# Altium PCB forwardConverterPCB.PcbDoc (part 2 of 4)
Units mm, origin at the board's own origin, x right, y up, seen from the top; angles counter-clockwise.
Board outline 382.81 x 370.12 mm, 8 copper layers (L1, L2 (GND), L3, L4, L5(GND), L6, L7 (GND), L8), stack 1.028 mm thick; 352 components, 187 nets, 1188 pads, 1016 vias.
Unrouted connection lines stored in the file: 19.
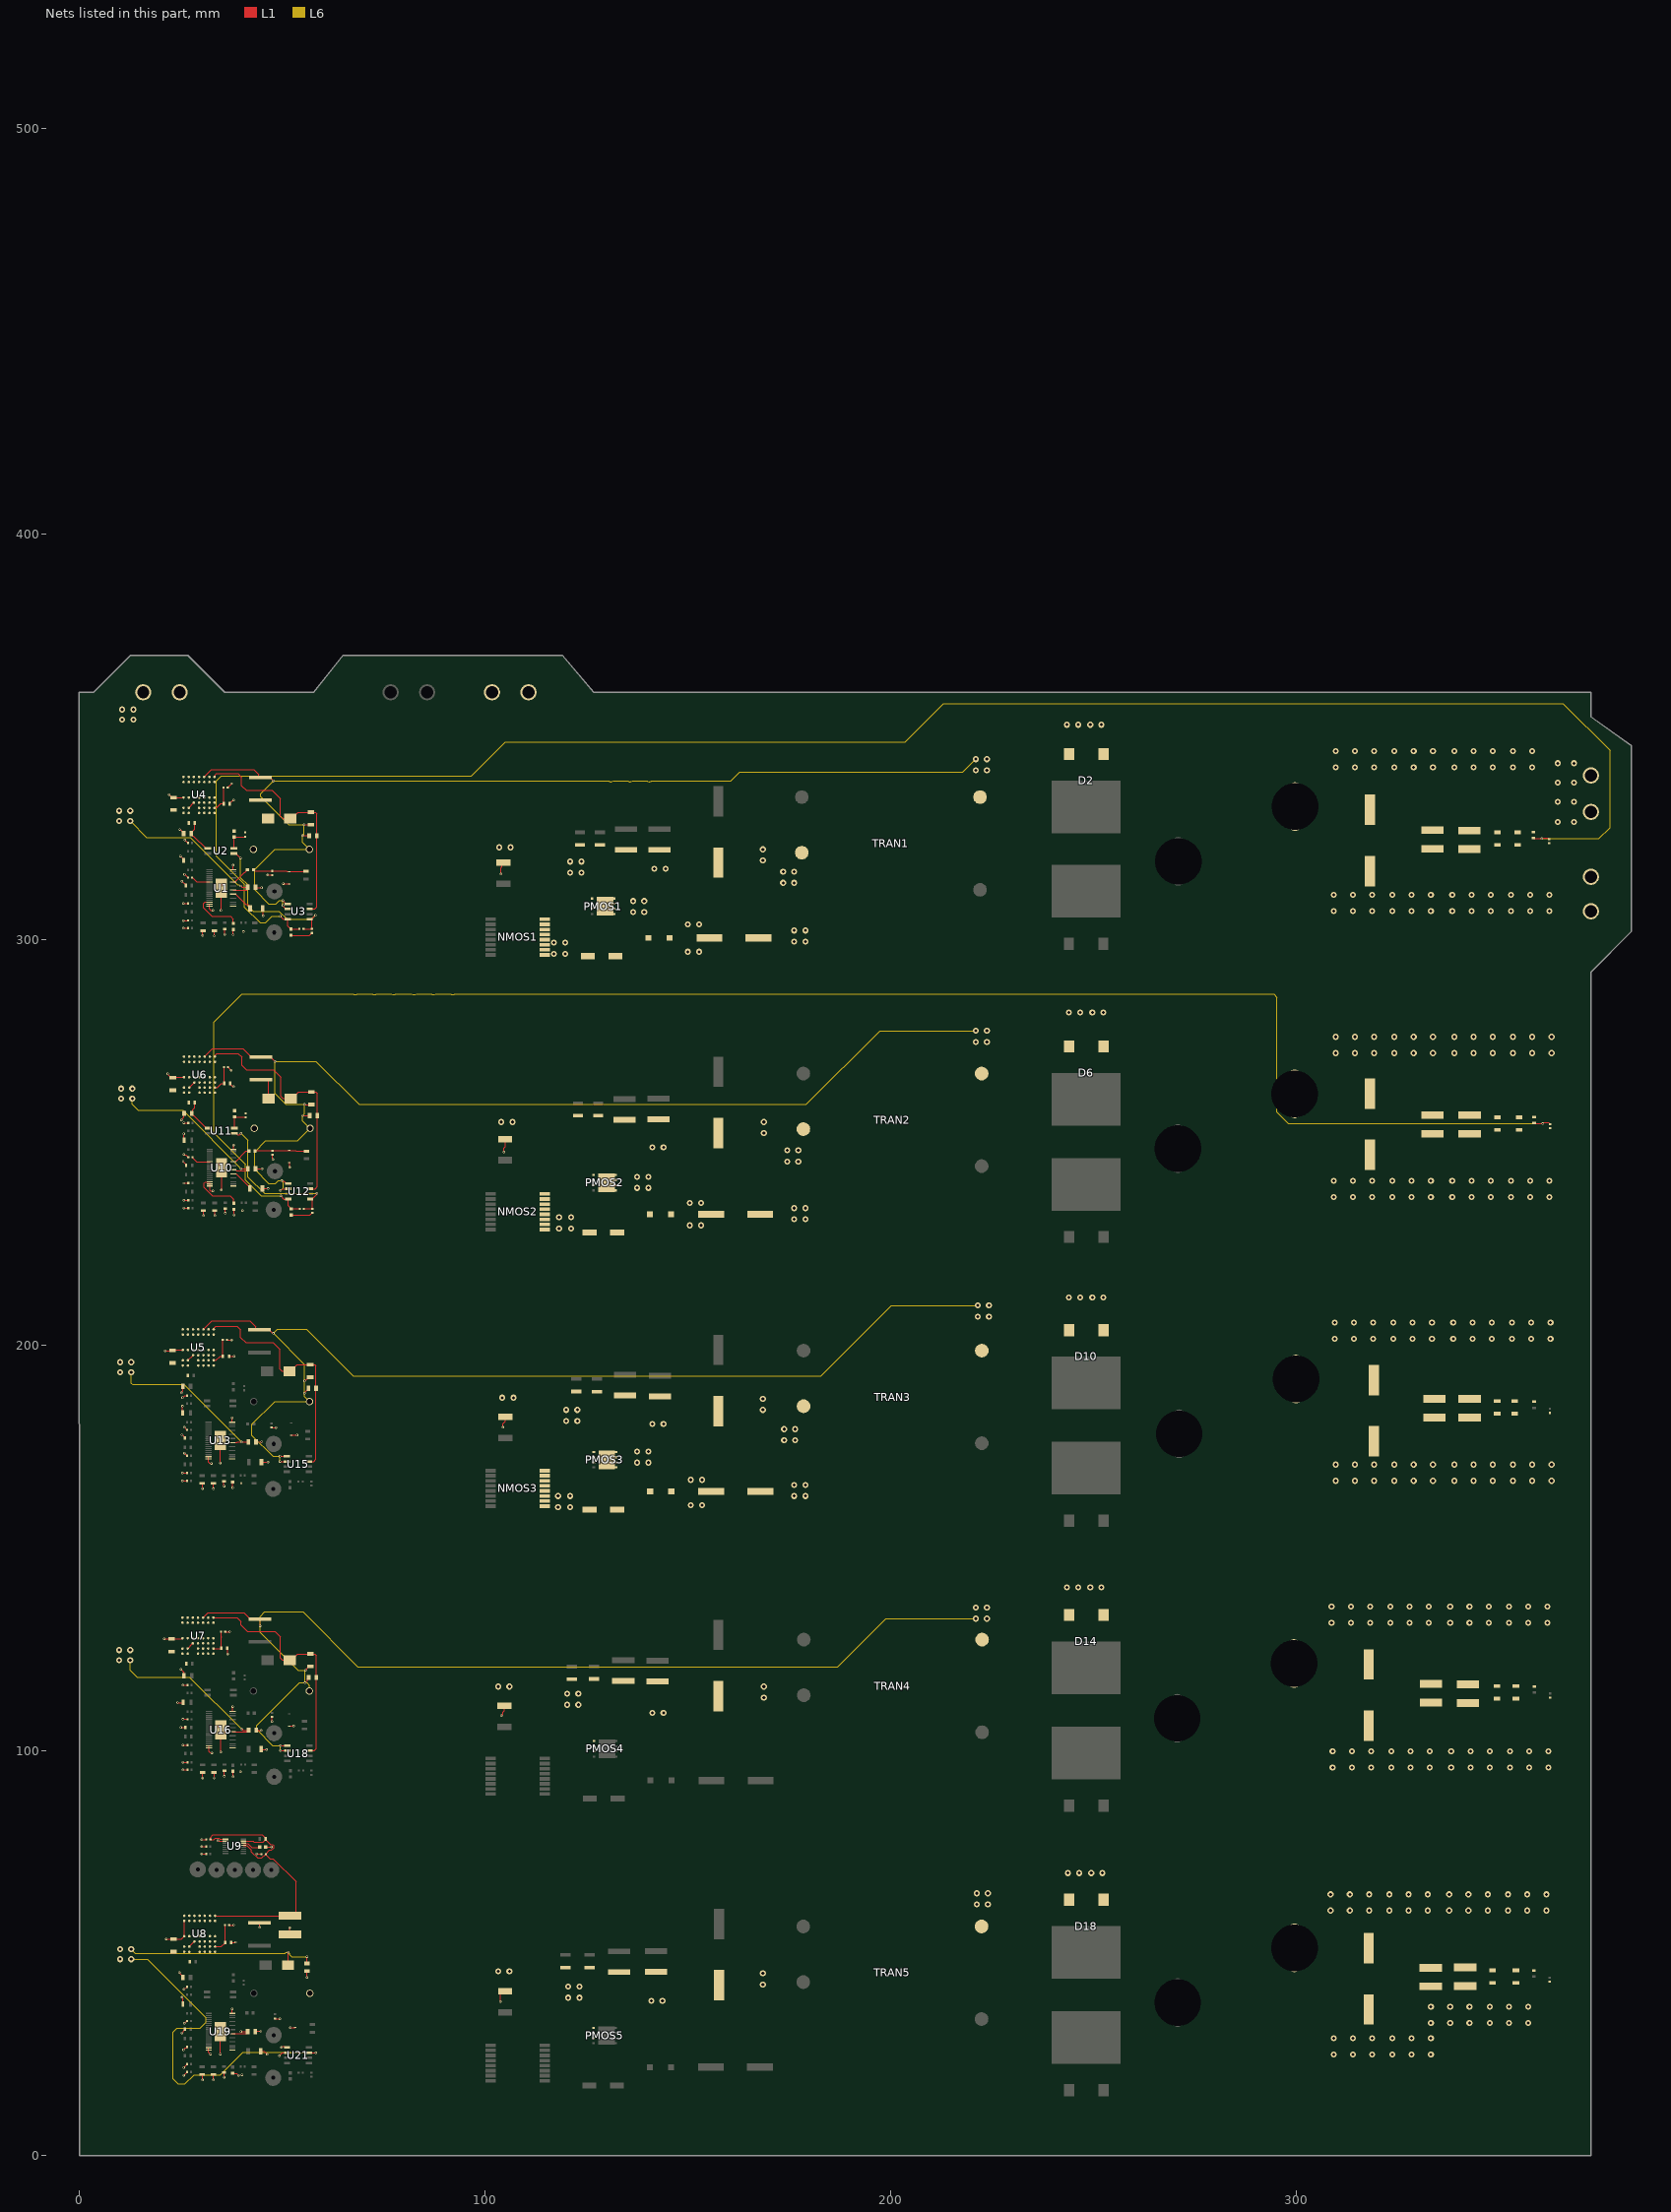
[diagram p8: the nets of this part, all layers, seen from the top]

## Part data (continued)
C25 C27 C31 C33 C38: "50V 10uF X7R ±10% 1206 Multilayer Ceramic Capacitors MLCC - SMD/SMT ROHS", Case Code (Imperial)=1206, Case Code (Metric)=3216, Dielectric=X7R, Dielectric Material=Ceramic, Manufacturer="Samsung Electro-Mechanics", Max Operating Temperature=125°C, Min Operating Temperature=-55°C, Supplier Part Number=1276-6767-1-ND, Tolerance=10%, Voltage Rating=50V
C28 C29 C34 C35 C41: "0402 10 pF 6.3 V ±10 % Tolerance C0G/NP0 SMT Multilayer Ceramic Capacitor", Case Code (Imperial)=0402, Case Code (Metric)=1005, Dielectric=C0G, Dielectric Material=Ceramic, Manufacturer="KYOCERA AVX", Max Operating Temperature=125°C, Min Operating Temperature=-55°C, Supplier Part Number=478-12646-1-ND, Tolerance=10%, Voltage Rating=6.3V
C36 C37: "10V 100nF X7R ±10% 0402 Multilayer Ceramic Capacitors MLCC - SMD/SMT ROHS", Dielectric Material=Ceramic, Manufacturer="Cal-Chip Electronics", Max Operating Temperature=125°C, Min Operating Temperature=-55°C, Supplier Part Number=4713-GMC04X7R104K10NTCT-ND, Voltage Rating (DC)=10V
D1 D2 D5 D6 D9 D10 D13 D14 D17 D18: library part DSEP60-06AZ-TRL, "Power Diode Discretes-FRED TO-", Manufacturer=IXYS, Supplier Part Number=238-DSEP60-06AZ-TRLCT-ND
D3 D7 D11 D15 D19: "Rectifier Diode, Schottky, 1 Phase, 1 Element, 0.5A, 100V V(RRM), Silicon", Forward Voltage=850mV, Manufacturer=MCC, Max Forward Surge Current (Ifsm)=5.5A, Max Operating Temperature=150°C, Max Output current=500mA, Min Breakdown Voltage=100V, Min Operating Temperature=-55°C, Peak Reverse Current=1µA, Supplier Part Number=353-B05100W-TPCT-ND
D4 D8 D12 D16 D20: "Zener Diode Single 4.7V 5% 2Ohm 5000mW 2-Pin Case 017AA-01 T/R / DIODE ZENER 4.7V 5W AXIAL", Case/Package=Axial, Forward Voltage=1.2V, Manufacturer=onsemi, Manufacturer Lifecycle Status=ACTIVE, Max Operating Temperature=200°C, Max Power Dissipation=5W, Max Reverse Leakage Current=5µA, Min Operating Temperature=-65°C, Reference Voltage=4.7V, Supplier Part Number=1N5337, Test Current=260mA, Tolerance=5%
J1 J2 J3 J4 J5 J6 J7 J8 J9 J10: "ReelFast Surface Mount Nuts and Spacers/Standoffs -br Type SMTSO - Unified", Current Rating=36A, Manufacturer=PennEngineering, Supplier Part Number=153-SMTSO-116-8ET
L1 L2 L3 L4 L5: "Fixed Ind 33UH 52A 1.88 Mohm Th", Manufacturer=Codaca, Supplier Part Number=4044-CPEX4141L-330MC-ND
NMOS1 NMOS2 NMOS3 NMOS4 NMOS5: "Mosfet N-ch 200V 130A 280W Tolt", Manufacturer=GoFord, Supplier Part Number=3141-GT100N20TTCT-ND
PMOS1 PMOS2 PMOS3 PMOS4 PMOS5: "P-150V, -60A, RD(max) Less Than 80mOhm at -10V, VTH -1V to -4V, DFN5x6-8L", Manufacturer=GoFord, Manufacturer Lifecycle Status=ACTIVE, Supplier Part Number=3141-G900P15D5CT-ND
R1 R34 R59 R84 R109: "SM Series 3.9 Ohm ±5 % 2 W ±200 ppm/°C Surface Mount Wirewound Resistor", Case Code (Imperial)=2616, Case Code (Metric)=6740, Insulation Resistance=10GΩ, Manufacturer="TE Connectivity", Manufacturer Lifecycle Status=ACTIVE, Max Operating Temperature=275°C, Max Power Dissipation=2W, Min Operating Temperature=-55°C, Number of Resistors=1, Operating Supply Voltage=300V, Supplier Part Number=A103596DKR-ND, Temperature Coefficient=200ppm/°C, Tolerance=5%
R2 R35 R60 R85 R110: "Res Thick Film 0805 82.5K Ohm 1% 1/8W ±100ppm/°C Molded SMD SMD Paper T/R", Case Code (Imperial)=0805, Case Code (Metric)=2012, Manufacturer="Stackpole Electronics", Max Operating Temperature=155°C, Max Power Dissipation=125mW, Min Operating Temperature=-55°C, Supplier Part Number=RMCF0805FT82K5CT-ND, Temperature Coefficient=100ppm/°C, Tolerance=1%, Voltage Rating=150V
R3 R7 R24 R25 R36 R40 R57 R58 R61 R65 R82 R83 R86 R90 R107 R108 R111 R115 R132 R133: "Zero Ohm Resistor, Jumper, 0805 [2012 Metric], Thick Film, 125 mW, 2.5 A, Surface Mount Device", Case Code (Imperial)=0805, Manufacturer=Vishay, Manufacturer Package Identifier=CRCW0805-e3, Max Operating Temperature=155°C, Max Power Dissipation=125mW, Min Operating Temperature=-55°C, Supplier Part Number=541-0.0ADKR-ND, Temperature Coefficient=100ppm/°C, Tolerance=1%, Voltage Rating=150V
R4 R23 R30 R31 R37 R56 R62 R81 R87 R106 R112 R131: "Fixed Resistor, Metal Glaze/thick Film, 0.0625W, 10000ohm, 50V, 1% +/-Tol, Surface Mount, 0402", Case/Package=0402, Manufacturer="Cal-Chip Electronics", Max Operating Temperature=155°C, Min Operating Temperature=-55°C, Power Dissipation=62.5mW, Power Rating=63mW, Supplier Part Number=4713-RM04F1002CT-ND, Temperature Coefficient=100ppm/°C, Tolerance=1%, Voltage Rating=50V
R5 R38 R63 R88 R113: "100mW Thick Film Resistors 75V ±100ppm/℃ ±1% 37.4kΩ 0603 Chip Resistor - Surface Mount ROHS", Case Code (Imperial)=0603, Manufacturer="Yageo Group", Max Operating Temperature=155°C, Max Power Dissipation=100mW, Min Operating Temperature=-55°C, Supplier Part Number=311-37.4KHRCT-ND, Temperature Coefficient=100ppm/°C, Tolerance=1%, Voltage Rating=75V, Voltage Rating (DC)=50V
R6 R39 R64 R89 R114: "Res Thick Film 0603 78.7K Ohm 1% 0.1W(1/10W) ±100ppm/C Pad SMD T/R", Case Code (Imperial)=0603, Manufacturer="Yageo Group", Max Operating Temperature=155°C, Max Power Dissipation=100mW, Min Operating Temperature=-55°C, Supplier Part Number=311-78.7KHRCT-ND, Temperature Coefficient=100ppm/°C, Tolerance=1%, Voltage Rating=75V, Voltage Rating (DC)=50V
R8 R41 R66 R91 R116: "Yageo RC0603FR-07100RL 0603 SMD Resistor 100 Ohm thin film chip resistor", Case Code (Imperial)=0603, Manufacturer="Yageo Group", Max Operating Temperature=155°C, Min Operating Temperature=-55°C, Power Dissipation=100mW, Supplier Part Number=311-100HRCT-ND, Temperature Coefficient=100ppm/°C, Tolerance=1%, Voltage Rating=75V, Voltage Rating (DC)=50V
R9 R11 R42 R44 R67 R69 R92 R94 R117 R119: "Res Thin Film 0402 5K Ohm 0.1% 0.05W(1/20W) +/-25ppm/C Sulfur Resistant Pad SMD Medical T/R", Case Code (Imperial)=0402, Case Code (Metric)=1005, Manufacturer=Vishay, Max Operating Temperature=155°C, Max Power Dissipation=50mW, Min Operating Temperature=-55°C, Supplier Part Number=541-1901-1-ND, Temperature Coefficient=25ppm/°C, Tolerance=0.1%, Working Voltage=75V
R10 R43 R68 R93 R118: "Res Thick Film 2512 1m Ohm 1% 2W ±75ppm/°C Molded SMD Embossed T/R", Case Code (Imperial)=2512, Case Code (Metric)=6432, Manufacturer=Bourns, Max Operating Temperature=170°C, Max Power Dissipation=2W, Min Operating Temperature=-55°C, Supplier Part Number=CRE2512-FZ-R001E-2CT-ND, Temperature Coefficient=50ppm/°C, Tolerance=1%
R12 R45 R70 R95 R120: "Res Thick Film 0603 13.3K Ohm 1% 0.1W(1/10W) ±100ppm/C Pad SMD Automotive T/R", Case Code (Imperial)=0603, Case Code (Metric)=1608, Manufacturer="Stackpole Electronics", Max Operating Temperature=155°C, Max Power Dissipation=100mW, Min Operating Temperature=-55°C, Supplier Part Number=RMCF0603FT13K3CT-ND, Temperature Coefficient=100ppm/°C, Tolerance=1%, Voltage Rating=75V
R13 R17 R18 R19 R46 R50 R51 R52 R71 R75 R76 R77 R96 R100 R101 R102 R121 R125 R126 R127: "62.5mW Thick Film Resistors ±100ppm/℃ ±1% 1kΩ 0402 Chip Resistor - Surface Mount ROHS", Manufacturer="Cal-Chip Electronics", Max Operating Temperature=155°C, Min Operating Temperature=-55°C, Power Dissipation=62.5mW, Supplier Part Number=4713-RM04F1001CT-ND, Temperature Coefficient=100ppm/°C, Tolerance=1%, Working Voltage=50V
R14 R47 R72 R97 R122: "Res Thick Film 0402 3K Ohm 1% 0.063W(1/16W) ±100ppm/C Pad SMD Automotive T/R", Case Code (Imperial)=0402, Case Code (Metric)=1005, Manufacturer="Yageo Group", Max Operating Temperature=155°C, Max Power Dissipation=63mW, Min Operating Temperature=-55°C, Power Dissipation=62.5mW, Supplier Part Number=YAG3485CT-ND, Temperature Coefficient=100ppm/°C, Tolerance=1%, Voltage Rating=50V
R15 R16 R48 R49 R73 R74 R98 R99 R123 R124: "Fixed Resistor, Metal Glaze/thick Film, 0.0625W, 100000ohm, 50V, 1% +/-Tol, Surface Mount, 0402", Manufacturer="Cal-Chip Electronics", Max Operating Temperature=155°C, Min Operating Temperature=-55°C, Power Dissipation=62.5mW, Supplier Part Number=4713-RM04F1003CT-ND, Temperature Coefficient=100ppm/°C, Tolerance=1%, Working Voltage=50V
R20 R53 R78 R103 R128: "Fixed Resistor, Wire Wound, 1W, 500ohm, 22.3607V, 1% +/-Tol, 20ppm/Cel, Surface Mount, 2515", Case Code (Imperial)=2515, Case Code (Metric)=6438, Manufacturer=Vishay, Max Operating Temperature=275°C, Min Operating Temperature=-65°C, Power Dissipation=1W, Supplier Part Number=541-WSC2515500R0FEBCT-ND, Temperature Coefficient=20ppm/°C, Tolerance=1%, Working Voltage=22.3607V
R21 R54 R79 R104 R129: "100mW Thick Film Resistors 75V ±100ppm/℃ ±1% 150kΩ 0603 Chip Resistor - Surface Mount ROHS", Case Code (Imperial)=0603, Manufacturer="Yageo Group", Max Operating Temperature=155°C, Max Power Dissipation=100mW, Min Operating Temperature=-55°C, Supplier Part Number=311-150KHRCT-ND, Temperature Coefficient=100ppm/°C, Tolerance=1%, Voltage Rating=75V, Voltage Rating (AC)=50V
R22 R55 R80 R105 R130: "Res Thick Film 0603 75K Ohm 1% 0.1W(1/10W) ±100ppm/C Pad SMD T/R Automotive AEC-Q200", Case Code (Imperial)=0603, Case Code (Metric)=1608, Manufacturer="Yageo Group", Max Operating Temperature=155°C, Max Power Dissipation=100mW, Min Operating Temperature=-55°C, Supplier Part Number=YAG3629CT-ND, Temperature Coefficient=100ppm/°C, Tolerance=1%, Voltage Rating=75V
R26 R27 R28 R29: "Fixed Resistor, Metal Glaze/thick Film, 0.1W, 3480ohm, 75V, 1% +/-Tol, Surface Mount, 0603", Manufacturer="Cal-Chip Electronics", Max Operating Temperature=155°C, Min Operating Temperature=-55°C, Power Dissipation=100mW, Supplier Part Number=4713-RM06F3481CT-ND, Temperature Coefficient=100ppm/°C, Tolerance=1%, Working Voltage=75V
R32: "100mW Thick Film Resistors 75V ±100ppm/℃ ±1% 402kΩ 0603 Chip Resistor - Surface Mount ROHS", Case Code (Imperial)=0603, Manufacturer="Yageo Group", Max Operating Temperature=155°C, Max Power Dissipation=100mW, Min Operating Temperature=-55°C, Supplier Part Number=311-402KHRCT-ND, Temperature Coefficient=100ppm/°C, Tolerance=1%, Voltage Rating=75V, Voltage Rating (DC)=50V
R33: "Res Thick Film 0603 11.8K Ohm 1% 0.1W(1/10W) ±100ppm/C Pad SMD Automotive T/R", Case Code (Imperial)=0603, Case Code (Metric)=1608, Manufacturer="KOA Speer", Max Operating Temperature=155°C, Min Operating Temperature=-55°C, Power Dissipation=100mW, Supplier Part Number=2019-RK73H1JTTD1182FCT-ND, Temperature Coefficient=100ppm/°C, Tolerance=1%, Voltage Rating=75V, Voltage Rating (DC)=50V
TRAN1 TRAN2 TRAN3 TRAN4 TRAN5: "Transformer, planar, for TI UCC28950, SMT, RoHS", Manufacturer=Coilcraft, Max Operating Temperature=120°C, Max Supply Voltage=60V, Min Input Voltage=38V, Min Operating Temperature=-40°C, Power Rating=800W
U1 U10 U13 U16 U19: "500kHz 8.5V~100V Buck-boost type 1 TSSOP-38-EP-4.4mm DC-DC Controllers ROHS", Case/Package=TSSOP, Frequency=500kHz, Manufacturer="Analog Devices", Manufacturer Lifecycle Status=PRODUCTION, Max Operating Temperature=150°C, Max Supply Voltage=100V, Min Operating Temperature=-40°C, Min Supply Voltage=8.5V, Nominal Supply Voltage=12V, Supplier Part Number=LT3753HFE#PBF-ND
U2 U11 U14 U17 U20: "Optocoupler DC-IN 1-CH Transistor DC-OUT 4-Pin SSOP T/R", Case/Package=SSOP, Collector Emitter Breakdown Voltage=80V, Collector Emitter Saturation Voltage=300mV, Current Transfer Ratio=50%, Dark Current=100nA, Forward Current=30mA, Forward Voltage=1.4V, Input Current=5mA, Isolation Voltage=2.5kV, Manufacturer=Renesas, Manufacturer Lifecycle Status=ACTIVE, Max Operating Temperature=100°C, Max Power Dissipation=120mW, Min Operating Temperature=-55°C, Reverse Breakdown Voltage=6V, Supplier Part Number=559-1038-1-ND
U3 U12 U15 U18 U21: "V-Ref Adjustable 2.5V to 36V 100mA 8-Pin SOIC N T/R", Cathode Current=1mA, Manufacturer="Analog Devices", Manufacturer Lifecycle Status=PRODUCTION, Max Operating Temperature=70°C, Max Output Voltage=36V, Min Operating Temperature=0°C, Min Output Voltage=2.5V, Output Current=100mA, Supplier Part Number=LT1431CS8#TRPBFCT-ND, Temperature Coefficient=30ppm/°C, Tolerance=0.4%
U4 U5 U6 U7 U8: "Module DC-DC 1-OUT 2.5V to 24V 0.45A 2.5W 38-Pin BGA Tray", Case/Package=BGA, Isolation Voltage=2kV, Manufacturer="Analog Devices", Manufacturer Lifecycle Status=PRODUCTION, Manufacturer Part Number=LTM8067EY#PBF67, Max Junction Temperature (Tj)=125°C, Max Output current=450mA, Max Output Voltage=24V, Max Supply Voltage=40V, Min Input Voltage=2.8V, Min Operating Temperature=-40°C, Min Output Voltage=2.5V, Min Supply Voltage=3V, Nominal Supply Current=7mA, Supplier Part Number=505-LTM8067EY#PBF-ND
U9: "1 to 8 Output, Multiphase Silicon Oscillator with Spread Spectrum Modulation", Case/Package=MSOP, Frequency=6.67MHz, Manufacturer="Analog Devices", Manufacturer Lifecycle Status=PRODUCTION, Max Junction Temperature (Tj)=150°C, Max Operating Temperature=125°C, Max Supply Voltage=5.5V, Min Operating Temperature=-40°C, Min Supply Voltage=2.7V, Operating Supply Current=2.4mA, Supplier Part Number=505-LTC6909HMS#TRPBFCT-ND

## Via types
v1: diameter 1.5, hole 0.75, L1 to L8, tented both sides, 800 vias
v2: diameter 0.6, hole 0.3, L1 to L8, tented both sides, 216 vias

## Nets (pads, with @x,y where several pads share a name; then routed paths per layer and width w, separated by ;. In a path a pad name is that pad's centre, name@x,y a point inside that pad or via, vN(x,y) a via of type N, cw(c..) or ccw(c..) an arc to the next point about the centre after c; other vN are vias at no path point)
+3.3V: C36.2 C37.2 C39.2 R32.1 U8.A6 U8.A7 U8.B6 U8.B7 U9.1 U9.13 U9.15 | length 76.5
  L1 w0.2: C37.2@32.285,78.023 33.186,78.023 33.463,78.3 34.349,78.3 34.536,78.113 U9.1@35.987,78.113 ; C37.2@32.285,78.113 32.285,78.535 32.9,79.15 45.05,79.15 45.9,78.3 R32.1@45.9,78.15 ; U8.A7@33.42,59.23 51.87,59.23 C39.2@51.9,59.2 53.4,59.2 53.4,67.652 47.752,73.3 47.008,73.3 C36.2@45.908,74.4 ; U9.13@40.411,76.613 40.461,76.563 41.248,76.563 42.35,75.461 42.35,75.002 43.901,73.45 44.958,73.45 C36.2@45.908,74.4 ; U9.15@40.411,77.613 42.818,77.613 43.03,77.4 45.3,77.4 45.9,78 47.1,76.8 47.6,76.8 47.9,76.5 47.9,75.951 47.341,75.392 46.9,75.392 C36.2@45.908,74.4
+12V: C13.2 C24.2 C26.2 C30.2 C32.2 C38.2 C54.2 C77.2 C100.2 C123.2 C133.2 J3.1 R8.2 R41.2 R66.2 R91.2 R116.2 R128.2 U1.28 U4.F3 U4.G1 U4.G2 U4.H1 U4.H2 U5.F3 U5.G1 U5.G2 U5.H1 U5.H2 U6.F3 U6.G1 U6.G2 U6.H1 U6.H2 U7.F3 U7.G1 U7.G2 U7.H1 U7.H2 U8.F3 U8.G1 U8.G2 U8.H1 U8.H2 U10.28 U13.28 U16.28 U19.28 U21.3 | length 313.4
  L1 w0.2: U7.G2@26.657,125.138 U7.F3@27.927,126.408 ; U5.G2@26.727,196.23 U5.F3@27.997,197.5 ; U4.G2@26.934,332.511 U4.F3@28.204,333.781 ; U6.G2@27.037,263.504 U6.F3@28.307,264.774 ; U8.G2@27.07,51.61 U8.F3@28.34,52.88 ; U13.28@37.65,175.942 38.892,175.942 39.007,176.057 v2(39.947,176.057) 41.618,176.057 C77.2@41.625,176.05 ; U19.28@37.663,30.121 41.1,30.121 41.45,30.471 C123.2@41.45,30.65 39.779,30.65 v2(39.772,30.657) ; U16.28@37.754,104.603 41.324,104.603 C100.2@41.674,104.953 ; U1.28@37.857,312.223 41.223,312.223 41.223,312.673 C13.2@41.475,312.925 40.083,312.925 39.783,313.225 v2(39.675,313.225) ; U10.28@37.96,243.216 38.57,243.216 38.61,243.176 38.61,243.117 38.727,243 41.15,243 41.5,243.35 C54.2@41.5,243.5 39.829,243.5 v2(39.822,243.507) ; v2(39.9,105.3) 40.008,105.3 40.356,104.953 C100.2@41.674,104.953 ; C100.2@41.674,105.003 C100.2@41.674,104.953 ; R128.2@51.425,47.025 51.475,47.075 v2(51.475,50.225) ; C133.2@56.1,47.45 56.1,49.121 v2(56.107,49.128) ; U21.3@56.575,25.448 58.246,25.448 v2(58.253,25.441)
  L6 w0.2: v1(12.5,122.25) 12.5,119.741 14.183,118.058 14.225,118.1 27.1,118.1 v2(39.9,105.3) ; v1(12.5,329.25) 16.55,325.2 27.3,325.2 38.98,313.52 39.358,313.52 39.653,313.225 v2(39.675,313.225) ; v1(12.75,48.5) 16.75,48.5 31.25,34 31.25,33 29.75,31.5 24,31.5 23,30.5 23,19 24.25,17.75 26,17.75 28.25,20 34.75,20 40.35,25.6 52.018,25.6 52.178,25.441 v2(58.253,25.441) ; v1(12.75,51) 13.75,50 50.775,50 50.923,50.148 51.398,50.148 v2(51.475,50.225) 51.475,50.166 51.87,49.771 51.87,49.63 52.372,49.128 v2(56.107,49.128) ; v1(12.75,193.25) 12.75,190.575 13.05,190.275 25.729,190.275 v2(39.947,176.057) ; v1(13,260.75) 13,259.35 14.45,257.9 25.429,257.9 v2(39.822,243.507)
  other v1: 10,48.5 10,51 9.75,122.25 9.75,124.75 12.5,124.75 10,193.25 10,195.75 12.75,195.75 10.25,260.75 10.25,263.25 13,263.25 9.75,329.25 9.75,331.75 12.5,331.75 10.5,354.25 13.25,354.25 10.5,356.75 13.25,356.75
+PH2: C2.2 C7.1 C8.1 C9.1 C10.1 C22.1 C23.1 C25.1 C43.1 C48.2 C49.2 C50.2 C51.2 D2.1 D2.3 D4.2 L2.2 R19.1 R45.2 TRAN1.11 U3.5 U3.6 U4.A1 U4.A2 U4.A3 U4.A4 U4.A5 U4.B1 U4.B2 U4.B3 U4.B4 U4.B5 | length 257.9
  L1 w0.2: U4.A5@30.744,340.131 32.563,341.95 42.975,341.95 44.175,340.75 44.175,340.373 44.525,340.023 46.977,340.023 47.825,339.175 v2(47.85,339.175) ; v2(50.125,309.625) 50.125,309.602 50.907,308.82 U3.5@51.345,308.82 ; v2(50.175,308.45) 50.252,308.373 50.252,308.205 50.907,307.55 U3.6@51.345,307.55 ; v2(54.949,325.63) 54.956,325.623 C23.1@56.627,325.623 ; v2(55.399,328.33) 55.406,328.323 C25.1@57.077,328.323
  L6 w0.2: v2@50,309.5 v2(50.125,309.625) 49.25,309.625 48.452,308.827 46.623,308.827 43.175,312.275 43.175,317.25 48.178,322.253 D4.2@56.664,322.253 54.949,323.969 v2(54.949,325.63) 55.399,326.08 v2(55.399,328.33) 51.545,328.33 44.62,335.255 44.62,335.945 47.875,339.2 130.32,339.2 ccw(c131,340) 131.68,339.2 135.07,339.2 ccw(c135.75,340) 136.43,339.2 139.82,339.2 ccw(c140.5,340) 141.18,339.2 160.675,339.2 162.811,341.336 217.836,341.336 v1(221,344.5) ; v2@50.09,309.5 50.15,309.44 50.15,308.475 v2(50.175,308.45)
  other v1: 309.75,272 314.5,272 319.25,272 324.25,272 329,272 333.75,272 339,272 343.75,272 348.5,272 353.5,272 358.25,272 363,272 309.75,276 314.5,276 319.25,276 324.25,276 329,276 333.75,276 339,276 343.75,276 348.5,276 353.5,276 358.25,276 363,276 309.25,307 314,307 318.75,307 323.75,307 328.5,307 333.25,307 338.5,307 343.25,307 348,307 353,307 357.75,307 362.5,307 309.25,311 314,311 318.75,311 323.75,311 328.5,311 333.25,311 338.5,311 343.25,311 348,311 353,311 357.75,311 362.5,311 221,341.75 223.75,341.75 223.75,344.5 243.5,353 246.25,353 249.25,353 252,353
+PH3: C31.1 C43.2 C48.1 C49.1 C50.1 C51.1 C63.1 C64.1 C66.1 C71.2 C72.2 C73.2 C74.2 D6.1 D6.3 D8.2 L3.2 R52.1 R70.2 TRAN2.11 U6.A1 U6.A2 U6.A3 U6.A4 U6.A5 U6.B1 U6.B2 U6.B3 U6.B4 U6.B5 U12.5 U12.6 | length 266.4
  L1 w0.2: U6.A5@30.847,271.124 32.798,273.075 40.321,273.075 42.38,271.016 47.08,271.016 48.146,269.95 v2(48.15,269.95) ; v2(49.575,238.125) 49.588,238.125 50.006,238.543 U12.6@51.448,238.543 ; v2(49.85,240.525) 49.927,240.448 50.374,240.448 51.01,239.813 U12.5@51.448,239.813 ; v2(55.052,256.623) 55.059,256.616 C64.1@56.73,256.616 ; v2(55.502,259.323) 55.509,259.316 C31.1@57.18,259.316
  L6 w0.2: v2(49.575,238.125) 50.225,238.775 50.225,240.15 v2(49.85,240.525) 49.77,240.525 49,240.525 48.295,239.82 46.655,239.82 43.175,243.3 43.175,247.633 45.932,250.39 53.801,250.39 D8.2@56.864,253.453 55.052,255.265 v2(55.052,256.623) 55.502,257.073 v2(55.502,259.323) 50.852,259.323 48.15,262.025 v2(48.15,269.95) 58.325,269.95 68.95,259.325 179.25,259.325 197.425,277.5 v1(221,277.5)
  other v1: 309.5,201.5 314.25,201.5 319,201.5 324,201.5 328.75,201.5 333.5,201.5 338.75,201.5 343.5,201.5 348.25,201.5 353.25,201.5 358,201.5 362.75,201.5 309.5,205.5 314.25,205.5 319,205.5 324,205.5 328.75,205.5 333.5,205.5 338.75,205.5 343.5,205.5 348.25,205.5 353.25,205.5 358,205.5 362.75,205.5 309.25,236.5 314,236.5 318.75,236.5 323.75,236.5 328.5,236.5 333.25,236.5 338.5,236.5 343.25,236.5 348,236.5 353,236.5 357.75,236.5 362.5,236.5 309.25,240.5 314,240.5 318.75,240.5 323.75,240.5 328.5,240.5 333.25,240.5 338.5,240.5 343.25,240.5 348,240.5 353,240.5 357.75,240.5 362.5,240.5 221,274.75 223.75,274.75 223.75,277.5 244,282 246.75,282 249.75,282 252.5,282
+PH4: C27.1 C66.2 C71.1 C72.1 C73.1 C74.1 C86.1 C87.1 C89.1 C94.2 C95.2 C96.2 C97.2 D10.1 D10.3 D12.2 L4.2 R77.1 R95.2 TRAN3.11 U5.A1 U5.A2 U5.A3 U5.A4 U5.A5 U5.B1 U5.B2 U5.B3 U5.B4 U5.B5 U15.5 U15.6 | length 262.4
  L1 w0.2: U5.A5@30.537,203.85 32.612,205.925 42.025,205.925 43.4,204.55 43.4,204.092 43.75,203.742 46.77,203.742 47.56,202.952 47.698,202.952 v2(47.775,202.875) ; v2(49.46,171.276) 49.467,171.269 U15.6@51.138,171.269 ; v2(49.46,172.546) 49.467,172.539 U15.5@51.138,172.539 ; v2(55.5,188.125) 55.5,188.222 56.42,189.142 C87.1@56.42,189.342 ; v2(55.525,191.125) 55.603,191.125 56.52,192.042 C27.1@56.87,192.042
  L6 w0.2: v2(49.46,171.276) v2(49.46,172.546) 47.663,172.546 42.5,177.709 42.5,180.4 48.153,186.053 D12.2@56.714,186.053 ; v2(55.5,188.125) 55.5,191.1 v2(55.525,191.125) 55.525,195.125 v2(47.775,202.875) 48.825,203.925 55.95,203.925 67.5,192.375 182.875,192.375 200.25,209.75 v1(221.5,209.75) ; v2@55.513,188.138 55.513,187.255 D12.2@56.564,186.203
  other v1: 308.75,131.5 313.5,131.5 318.25,131.5 323.25,131.5 328,131.5 332.75,131.5 338,131.5 342.75,131.5 347.5,131.5 352.5,131.5 357.25,131.5 362,131.5 308.75,135.5 313.5,135.5 318.25,135.5 323.25,135.5 328,135.5 332.75,135.5 338,135.5 342.75,135.5 347.5,135.5 352.5,135.5 357.25,135.5 362,135.5 309.75,166.5 314.5,166.5 319.25,166.5 324.25,166.5 329,166.5 333.75,166.5 339,166.5 343.75,166.5 348.5,166.5 353.5,166.5 358.25,166.5 363,166.5 309.75,170.5 314.5,170.5 319.25,170.5 324.25,170.5 329,170.5 333.75,170.5 339,170.5 343.75,170.5 348.5,170.5 353.5,170.5 358.25,170.5 363,170.5 221.5,207 224.25,207 224.25,209.75 244,211.75 246.75,211.75 249.75,211.75 252.5,211.75
+PH5: C33.1 C89.2 C94.1 C95.1 C96.1 C97.1 C109.1 C110.1 C112.1 C117.2 C118.2 C119.2 C120.2 D14.1 D14.3 D16.2 L5.2 R102.1 R120.2 TRAN4.11 U7.A1 U7.A2 U7.A3 U7.A4 U7.A5 U7.B1 U7.B2 U7.B3 U7.B4 U7.B5 U18.5 U18.6 | length 261.9
  L1 w0.2: U7.A5@30.467,132.758 31.709,134 40.577,134 42.174,132.403 C109.1@44.524,132.403 44.524,130.732 v2(44.517,130.725) ; v2(49.564,99.937) 49.571,99.93 U18.6@51.242,99.93 ; v2(49.564,101.207) 49.571,101.2 U18.5@51.242,101.2 ; v2(55.6,116.675) 56.174,117.249 56.174,117.653 C110.1@56.524,118.003 ; v2(55.7,119.775) 55.7,119.779 56.624,120.703 C33.1@56.974,120.703
  L6 w0.2: v2(49.564,99.937) v2(49.564,101.207) 47.645,101.207 43.725,105.126 43.725,106.175 54.225,116.675 v2(55.6,116.675) ; D16.2@56.664,114.653 56.664,116.046 56.042,116.669 55.606,116.669 v2(55.6,116.675) ; v1(221,132.5) 198.875,132.5 187.025,120.65 68.65,120.65 55.15,134.15 45.65,134.15 44.517,133.017 v2(44.517,130.725) 44.517,129.133 53.875,119.775 v2(55.7,119.775) 55.65,119.725 55.65,116.725 v2(55.6,116.675)
  other v1: 308.5,60.5 313.25,60.5 318,60.5 323,60.5 327.75,60.5 332.5,60.5 337.75,60.5 342.5,60.5 347.25,60.5 352.25,60.5 357,60.5 361.75,60.5 308.5,64.5 313.25,64.5 318,64.5 323,64.5 327.75,64.5 332.5,64.5 337.75,64.5 342.5,64.5 347.25,64.5 352.25,64.5 357,64.5 361.75,64.5 309,95.75 313.75,95.75 318.5,95.75 323.5,95.75 328.25,95.75 333,95.75 338.25,95.75 343,95.75 347.75,95.75 352.75,95.75 357.5,95.75 362.25,95.75 309,99.75 313.75,99.75 318.5,99.75 323.5,99.75 328.25,99.75 333,99.75 338.25,99.75 343,99.75 347.75,99.75 352.75,99.75 357.5,99.75 362.25,99.75 223.75,132.5 221,135.25 223.75,135.25 243.5,140.25 246.25,140.25 249.25,140.25 252,140.25
GND: C1.2 C3.1 C4.1 C5.1 C6.1 C13.1 C14.1 C18.1 C20.1 C21.1 C24.1 C26.1 C28.2 C29.2 C30.1 C32.1 C34.2 C35.2 C36.1 C37.1 C38.1 C39.1 C40.1 C41.2 C42.2 C44.1 C45.1 C46.1 C47.1 C54.1 C56.1 C59.1 C61.1 C62.1 C65.2 C67.1 C68.1 C69.1 C70.1 C77.1 C78.1 C82.1 C84.1 C85.1 C88.2 C90.1 C91.1 C92.1 C93.1 C100.1 C102.1 C105.1 C107.1 C108.1 C111.2 C112.2 C113.1 C114.1 C115.1 C116.1 C117.1 C118.1 C119.1 C120.1 C123.1 C124.1 C128.1 C130.1 C131.1 C132.1 C133.1 D3.1 D7.1 D11.1 D15.1 D18.1 D18.3 D19.1 D20.2 J6.1 J7.1 J8.1 J9.1 J10.1 PMOS1.1 PMOS1.2 PMOS1.3 PMOS2.1 PMOS2.2 PMOS2.3 PMOS3.1 PMOS3.2 PMOS3.3 PMOS4.1 PMOS4.2 PMOS4.3 PMOS5.1 PMOS5.2 PMOS5.3 R2.2 R4.1 R10.2 R13.1 R17.1 R18.1 R21.1 R22.1 R23.1 R24.1 R25.1 R26.2 R27.2 R28.2 R29.2 R30.1 R31.1 R33.2 R35.2 R37.1 R43.2 R46.1 R50.1 R51.1 R54.1 R55.1 R56.1 R57.1 R58.1 R60.2 R62.1 R68.2 R71.1 R75.1 R76.1 R79.1 R80.1 R81.1 R82.1 R83.1 R85.2 R87.1 R93.2 R96.1 R100.1 R101.1 R104.1 R105.1 R106.1 R107.1 R108.1 R110.2 R112.1 R118.2 R121.1 R125.1 R126.1 R127.1 R129.1 R130.1 R131.1 R132.1 R133.1 TRAN5.11 U1.18 U1.19 U1.20 U1.38 U1.39 U4.E1 U4.E2 U4.E3 U4.E4 U4.E5 U4.E6 U4.E7 U4.F4 U4.F5 U4.F6 U4.F7 U4.G4 U4.G5 U4.G6 U4.H4 U4.H5 U4.H6 U4.H7 U5.E1 U5.E2 U5.E3 U5.E4 U5.E5 U5.E6 U5.E7 U5.F4 U5.F5 U5.F6 U5.F7 U5.G4 U5.G5 U5.G6 U5.H4 U5.H5 U5.H6 U5.H7 U6.E1 U6.E2 U6.E3 U6.E4 U6.E5 U6.E6 U6.E7 U6.F4 U6.F5 U6.F6 U6.F7 U6.G4 U6.G5 U6.G6 U6.H4 U6.H5 U6.H6 U6.H7 U7.E1 U7.E2 U7.E3 U7.E4 U7.E5 U7.E6 U7.E7 U7.F4 U7.F5 U7.F6 U7.F7 U7.G4 U7.G5 U7.G6 U7.H4 U7.H5 U7.H6 U7.H7 U8.A1 U8.A2 U8.A3 U8.A4 U8.A5 U8.B1 U8.B2 U8.B3 U8.B4 U8.B5 U8.E1 U8.E2 U8.E3 U8.E4 U8.E5 U8.E6 U8.E7 U8.F4 U8.F5 U8.F6 U8.F7 U8.G4 U8.G5 U8.G6 U8.H4 U8.H5 U8.H6 U8.H7 U9.2 U10.18 U10.19 U10.20 U10.38 U10.39 U13.18 U13.19 U13.20 U13.38 U13.39 U16.18 U16.19 U16.20 U16.38 U16.39 U19.18 U19.19 U19.20 U19.38 U19.39 U21.5 U21.6 | length 218.9
  L1 w0.2: v2(20.9,127.5) C32.1@22.7,127.5 25.098,127.5 25.276,127.678 U7.E1@25.387,127.678 ; v2(21.1,198.6) 22.828,198.6 C30.1@22.92,198.692 22.998,198.77 U5.E1@25.457,198.77 ; v2(21.4,53.5) 23.1,53.5 C38.1@23.15,53.45 25.1,53.45 U8.E1@25.8,54.15 U8.B1@25.8,57.96 ; v2(21.775,266.9) 21.775,266.825 22.65,265.95 C26.1@23,265.95 23.094,266.044 U6.E1@25.767,266.044 ; v2(22.075,335.775) 22.125,335.775 22.85,335.05 C24.1@23.2,335.05 U4.E1@25.664,335.051 ; v2(24.2,111.8) 25.471,111.8 R85.2@25.574,111.903 ; v2(24.6,45.2) 24.6,45.104 25.483,44.221 C131.1@25.483,44.021 ; v2(24.7,327.175) 24.777,327.098 24.901,327.098 25.677,326.323 C21.1@25.677,326.123 ; v2(24.875,320.625) 25.677,319.823 R2.2@25.677,319.523 ; v2(24.947,105.68) 24.97,105.703 R104.1@26.074,105.703 ; v2(25,120) 25.75,119.25 C108.1@25.75,118.4 ; v2(25.1,188.2) 25.1,188.308 25.47,188.678 C85.1@25.47,189.842 ; v2(25.1,255.5) 25.78,256.18 C62.1@25.78,257.116 ; v2(25.225,30.325) 25.237,30.325 25.983,31.071 R129.1@25.983,31.221 ; v2(25.25,177.85) 25.312,177.85 25.97,177.192 R79.1@25.97,177.042 ; v2(25.25,314.375) 25.275,314.375 26.177,313.473 R21.1@26.177,313.323 ; v2(25.3,39.1) 25.3,38.992 25.483,38.809 R110.2@25.483,37.421 ; v2(25.393,166.519) 25.416,166.542 R81.1@26.52,166.542 ; v2(25.393,168.419) 25.416,168.442 R71.1@26.52,168.442 ; v2(25.4,184.9) 25.4,183.312 R60.2@25.47,183.242 ; v2(25.4,187) 25.942,187.542 R76.1@26.52,187.542 ; v2(25.473,116.077) 25.496,116.1 R101.1@26.6,116.1 ; v2(25.497,95.18) 25.52,95.203 R106.1@26.624,95.203 ; v2(25.497,97.08) 25.52,97.103 R96.1@26.624,97.103 ; v2(25.497,101.28) 25.52,101.303 R100.1@26.624,101.303 ; v2(25.497,107.68) 25.52,107.703 C105.1@26.624,107.703 ; v2(25.55,245.275) 25.55,245.196 26.28,244.466 R54.1@26.28,244.316 ; v2(25.6,302.8) 25.623,302.823 R23.1@26.727,302.823 ; v2(25.6,304.7) 25.623,304.723 R13.1@26.727,304.723 ; v2(25.6,308.9) 25.623,308.923 R17.1@26.727,308.923 ; v2(25.65,26.125) 26.146,26.621 26.383,26.621 26.533,26.771 R125.1@26.533,26.821 ; v2(25.7,19.875) 25.737,19.875 26.533,20.671 R131.1@26.533,20.721 ; v2(25.7,21.75) 25.712,21.75 26.533,22.571 R121.1@26.533,22.621 ; v2(25.7,252.1) 25.7,250.596 R35.2@25.78,250.516 ; v2(25.703,233.793) 25.726,233.816 R56.1@26.83,233.816 ; v2(25.703,235.693) 25.726,235.716 R46.1@26.83,235.716 ; v2(25.703,239.893) 25.726,239.916 R50.1@26.83,239.916 ; v2(25.703,254.793) 25.726,254.816 R51.1@26.83,254.816 ; v2(25.725,247) 25.802,246.923 26.222,246.923 C59.1@26.83,246.316 ; v2(25.775,41.075) 25.852,41.152 26.014,41.152 26.533,41.671 R126.1@26.533,41.721 ; v2(25.85,32.7) 26.221,33.071 26.383,33.071 C128.1@26.533,33.221 ; v2(25.875,179.675) 25.887,179.675 C82.1@26.52,179.042 ; v2(25.9,173.35) 25.9,173.312 26.52,172.692 R75.1@26.52,172.642 ; v2(25.9,316.05) 26,316.05 C18.1@26.727,315.323 ; v2(26,324.6) 26.727,323.873 R18.1@26.727,323.823 ; v2(30.15,74.5) 30.173,74.523 R31.1@31.277,74.523 ; v2(30.15,76.25) 30.173,76.273 R30.1@31.277,76.273 ; v2(30.15,78) 30.173,78.023 C37.1@31.277,78.023 ; R82.1@30.22,165.892 30.3,165.812 v2(30.3,164.6) ; R132.1@30.233,20.071 30.3,20.004 v2(30.3,18.7) ; R107.1@30.324,94.553 30.4,94.477 v2(30.4,93.2) ; v2(30.4,301) 30.4,302.146 R24.1@30.427,302.173 ; R57.1@30.53,233.166 30.6,233.096 v2(30.6,231.9) ; U13.18@31.82,172.442 U13.19@31.82,171.942 31.82,171.11 32.053,170.877 32.423,170.877 v2(32.5,170.8) ; U19.18@31.833,26.621 U19.19@31.833,26.121 31.833,25.567 v2(32.3,25.1) ; U16.18@31.924,101.103 U16.19@31.924,100.603 31.924,99.714 32.161,99.477 32.523,99.477 v2(32.6,99.4) ; U1.18@32.027,308.723 U1.19@32.027,308.223 32.027,307.517 32.3,307.244 32.856,307.244 v2(32.9,307.2) ; U10.18@32.13,239.716 U10.19@32.13,239.216 32.13,238.117 32.247,238 v2(32.9,238) ; v2(33,18.7) 33,20.038 R133.1@33.033,20.071 ; v2(33,164.5) 33,165.872 R83.1@33.02,165.892 ; R108.1@33.124,94.553 33.2,94.477 v2(33.2,93.2) ; v2(33.2,300.9) 33.2,302.146 R25.1@33.227,302.173 ; R58.1@33.33,233.166 33.4,233.096 v2(33.4,231.9) ; v2(34.1,77.7) 34.144,77.656 35.943,77.656 U9.2@35.987,77.613 ; v2(34.687,170.921) 34.735,170.969 U13.39@34.735,176.442 ; v2(34.7,25.1) 34.748,25.148 U19.39@34.748,30.621 ; v2(34.791,99.582) 34.839,99.63 U16.39@34.839,105.103 ; v2(34.894,307.202) 34.942,307.25 U1.39@34.942,312.723 ; v2(34.997,238.195) 35.045,238.243 U10.39@35.045,243.716 ; R80.1@35.62,166.342 35.62,165.237 v2(35.643,165.215) ; R130.1@35.633,20.521 35.633,19.416 v2(35.656,19.394) ; v2(35.7,93.6) 35.7,94.979 R105.1@35.724,95.003 ; v2(35.8,301.3) 35.8,302.596 R22.1@35.827,302.623 ; R55.1@35.93,233.616 35.93,232.511 v2(35.953,232.489) ; C35.2@35.932,129.26 37.036,129.26 v2(37.059,129.283) ; C29.2@36.328,201.242 37.432,201.242 v2(37.455,201.264) ; R29.2@36.45,125.25 36.5,125.2 v2(36.5,123.8) ; C28.2@36.535,337.523 37.475,338.463 v2(37.475,338.475) ; C34.2@36.638,268.516 37.354,267.8 v2(37.425,267.8) ; R27.2@36.87,197.242 36.912,197.2 v2(38.1,197.2) ; C41.2@36.908,56.9 38.012,56.9 v2(38.035,56.923) ; R26.2@37.077,333.523 37.077,333.673 37.753,334.348 37.923,334.348 v2(38,334.425) ; R28.2@37.18,264.516 37.18,264.366 37.769,263.777 37.898,263.777 v2(37.975,263.7) ; R33.2@37.4,52.65 38.504,52.65 v2(38.527,52.673) ; v2(37.627,182.069) 37.65,182.046 U13.38@37.65,180.942 ; v2(37.64,36.248) 37.663,36.225 U19.38@37.663,35.121 ; C84.1@37.72,166.192 37.8,166.112 v2(37.8,164.8) ; C130.1@37.733,20.371 38.704,20.371 v2(39.2,19.875) ; U16.38@37.754,109.603 37.76,109.603 37.8,109.643 v2(37.8,110.8) ; C107.1@37.824,94.853 37.9,94.777 v2(37.9,93.5) ; v2(37.834,318.35) 37.857,318.327 U1.38@37.857,317.223 ; v2(37.9,301.2) 37.9,302.446 C20.1@37.927,302.473 ; v2(37.937,249.343) 37.96,249.32 U10.38@37.96,248.216 ; C61.1@38.03,233.466 38.1,233.396 v2(38.1,232.1) ; C123.1@43.35,30.65 43.4,30.7 v2(44.7,30.7) ; C13.1@43.375,312.925 43.475,312.825 v2(44.875,312.825) ; C54.1@43.4,243.5 v2(45,243.5) ; C77.1@43.525,176.05 43.625,176.15 v2(44.925,176.15) ; C100.1@43.574,105.003 43.677,104.9 v2(44.8,104.9) ; v2(43.7,74.5) 43.75,74.45 44.85,74.45 C36.1@44.9,74.4 ; C132.1@44.4,57.45 44.4,56.346 v2(44.423,56.323) ; C124.1@44.683,25.821 45.479,25.821 v2(46.3,25) ; C102.1@44.774,100.303 44.877,100.2 v2(46.1,100.2) ; C78.1@44.85,171.125 46.438,171.125 v2(46.455,171.108) ; C56.1@45.1,238.6 45.116,238.584 v2(46.52,238.584) ; C14.1@45.15,307.725 45.273,307.602 v2(45.273,305.902) ; C40.1@45.9,76.15 45.95,76.2 v2(47.3,76.2) ; v2(46.4,315.9) 46.423,315.923 R4.1@47.527,315.923 ; R62.1@47.32,179.642 48.424,179.642 v2(48.447,179.664) ; R87.1@47.45,108.25 47.45,107.146 v2(47.473,107.123) ; R37.1@47.63,246.916 47.63,245.811 v2(47.653,245.789) ; R112.1@48.15,33.9 48.2,33.85 49.35,33.85 v2(49.4,33.8) ; v2(49.3,24.7) 50.048,25.448 U21.6@51.151,25.448 ; v2(49.806,26.725) 49.823,26.725 50.123,27.025 50.406,27.025 50.713,26.718 U21.5@51.151,26.718 ; v2(50.2,313.8) 50.25,313.75 D3.1@51.7,313.75 ; D15.1@51.7,106 52.804,106 v2(52.827,106.023) ; D7.1@51.7,245 51.8,245 v2(51.8,243.8) ; v2(51.8,56.3) 51.8,54.7 C39.1@51.9,54.6 ; v2(52,31.6) 52.05,31.65 D19.1@53.15,31.65 ; D11.1@52.2,177.75 53.55,177.75 v2(53.6,177.8) ; v2(56.1,44) C133.1@56.1,45.55 ; v2(103.75,38.025) 103.75,39.9 104.45,40.6 R118.2@104.95,40.6 ; v2(103.9,316.15) 103.9,317.675 104.215,317.99 104.215,318.61 R10.2@104.577,318.973 ; v2(104,108.575) 104.425,109 104.425,109.375 104.8,109.75 R93.2@104.8,111 ; 104.4,180 104.4,180.625 105,181.225 R68.2@105,182.3 ; v2@104.65,247.875 104.625,247.9 104.625,248.55 104.961,248.886 R43.2@104.961,250.79
  other v1: 309.25,25 314,25 318.75,25 323.75,25 328.5,25 333.25,25 309.25,29 314,29 318.75,29 323.75,29 328.5,29 333.25,29 333.25,32.75 338,32.75 342.75,32.75 347.75,32.75 352.5,32.75 357.25,32.75 333.25,36.75 338,36.75 342.75,36.75 347.75,36.75 352.5,36.75 357.25,36.75 141,38.25 143.75,38.25 120.5,39 123.25,39 120.5,41.75 123.25,41.75 168.5,42.25 168.5,45 103.25,45.5 106,45.5 221.25,62 224,62 221.25,64.75 224,64.75 243.75,69.75 246.5,69.75 249.5,69.75 252.25,69.75 141.25,109.25 144,109.25 120.25,111.25 123,111.25 168.75,113 120.25,114 123,114 103.25,115.75 106,115.75 168.75,115.75 141.25,180.5 144,180.5 120,181.25 122.75,181.25 120,184 122.75,184 168.5,184 168.5,186.75 104.25,187 107,187 141.25,248.75 144,248.75 168.75,252.25 104,255 106.75,255 168.75,255 121,316.5 123.75,316.5 141.75,317.5 144.5,317.5 121,319.25 123.75,319.25 168.5,319.5 168.5,322.25 103.5,322.75 106.25,322.75
  other v2: 40.075,20 39.65,94.725 39.875,165.85 104.375,179.675 40.2,233.175 104.625,247.625 40.45,301.95
NetC2_1: C2.1 C7.2 C8.2 C9.2 C10.2 J4.1 J5.1 L1.2 R12.2
  other v1: 364.5,329 368.5,329 364.5,334 368.5,334 364.5,338.75 368.5,338.75 309.75,342.5 314.5,342.5 319.25,342.5 324.25,342.5 329,342.5 333.75,342.5 339,342.5 343.75,342.5 348.5,342.5 353.5,342.5 358.25,342.5 364.5,343.5 368.5,343.5 309.75,346.5 314.5,346.5 319.25,346.5 324.25,346.5 329,346.5 333.75,346.5 339,346.5 343.75,346.5 348.5,346.5 353.5,346.5 358.25,346.5
NetC11_1: C11.1 R1.2
  other v1: 150,297 152.75,297 150,303.75 152.75,303.75
NetC11_2: C11.2 C12.2 NMOS1.9 NMOS1.10 NMOS1.11 NMOS1.12 NMOS1.13 NMOS1.14 NMOS1.15 NMOS1.16 TRAN1.4
  other v1: 117,296.5 119.75,296.5 117,299.25 119.75,299.25 176.25,299.5 179,299.5 176.25,302.25 179,302.25 173.5,314 176.25,314 173.5,316.75 176.25,316.75
NetC12_1: C12.1 PMOS1.5 PMOS1.6 PMOS1.7 PMOS1.8 R1.1
  other v1: 136.5,306.75 139.25,306.75 136.5,309.5 139.25,309.5
NetC14_2: C14.2 U1.26 | length 5.8
  L1 w0.2: U1.26@37.857,311.223 38.467,311.223 41.067,308.623 41.502,308.623 42.05,308.075 C14.2@42.05,307.725
NetC15_1: C15.1 U1.32 | length 4.8
  L1 w0.2: U1.32@37.857,314.223 38.467,314.223 38.507,314.263 38.507,314.353 40.707,316.552 40.727,316.552 C15.1@41.4,317.225
NetC15_2: C15.2 D3.2 R3.1 R4.2 | length 13.2
  L1 w0.2: C15.2@42.9,317.225 43.2,316.925 43.876,316.925 43.879,316.923 R4.2@47.527,316.923 50.975,316.923 51.148,316.75 D3.2@51.7,316.75 53.004,316.75 53.076,316.823 R3.1@55.827,316.823
NetC16_1: C16.1 R11.1 U2.3 U3.1 | length 39.6
  L1 w0.2: U2.3@38.049,321.23 38.549,321.23 39.654,320.125 v2(39.7,320.125) ; C16.1@55.227,302.623 R11.1@57.327,302.623 57.327,304.785 U3.1@57.102,305.01 ; U3.1@56.769,305.01 U3.1@57.102,305.01 ; v2(58.2,306) 58.197,306 57.207,305.01 U3.1@57.102,305.01
  L6 w0.2: v2(39.7,320.125) 39.7,315.25 41.475,313.475 41.475,308.35 42.8,307.025 49.2,307.025 51.222,305.003 57.203,305.003 v2(58.2,306)
NetC16_2: C16.2 C19.2 R12.1 R19.2 U3.8 | length 449.6
  L1 w0.2: v2(49.475,305.775) 50.24,305.01 U3.8@51.345,305.01 51.345,303.355 C19.2@52.127,302.573 52.177,302.623 C16.2@54.219,302.623 ; R12.1@358.5,325.05 358.65,324.9 360.708,324.9 360.908,325.1 362.083,325.1 362.2,324.983 362.2,324.95 362.35,324.8 R19.2@362.4,324.8
  L6 w0.2: v2(49.475,305.775) 47.477,305.775 45.885,304.183 44.517,304.183 40.725,307.975 40.725,313.6 33.8,320.525 33.8,339.2 34.9,340.3 96.575,340.3 104.975,348.7 203.575,348.7 213.1,358.225 365.8,358.225 377.4,346.625 377.4,327.6 374.7,324.9 v2(360.6,324.9)
NetC17_1: C17.1 R14.1 U2.4 | length 5.5
  L1 w0.2: U2.4@38.049,322.5 38.127,322.578 C17.1@38.127,325.273 40.673,325.273 R14.1@40.8,325.4
NetC17_2: C17.2 C22.2 D4.1 R14.2 R20.1
NetC18_2: C18.2 U1.7 | length 4.7
  L1 w0.2: C18.2@27.735,315.323 28.835,314.223 U1.7@32.027,314.223
NetC19_1: C19.1 R11.2 | length 5.4
  L1 w0.2: C19.1@52.127,301.073 56.727,301.073 57.277,301.623 R11.2@57.327,301.623
NetC20_2: C20.2 U1.17 | length 12.2
  L1 w0.2: U1.17@32.027,309.223 30.927,309.223 30.627,308.923 30.627,307.823 32.669,305.78 37.219,305.78 37.927,305.073 C20.2@37.927,303.973
NetC21_2: C21.2 R8.1 U2.1 | length 8.9
  L1 w0.2: R8.1@28.45,328.75 28.45,327.196 27.577,326.323 C21.2@27.577,326.123 ; U2.1@31.649,322.5 31.149,322.5 28.076,325.573 27.927,325.573 C21.2@27.577,325.923 ; C21.2@27.577,325.923 C21.2@27.577,326.123 ; C21.2@27.577,325.923 C21.2@27.577,326.123
NetC23_2: C23.2 C25.2 R20.2 U3.3 U4.A6 U4.A7 U4.B6 U4.B7 | length 59.9
  L1 w0.2: U4.A7@33.284,340.131 33.35,340.197 33.35,340.521 33.752,340.923 39.027,340.923 39.927,340.023 39.927,337.973 41.1,336.8 47.5,336.8 49.577,334.723 49.577,330.373 50.077,329.873 51.927,329.873 R20.2@51.977,329.823 52.277,329.823 53.877,331.423 C25.2@57.077,331.423 58.177,331.423 58.527,331.073 C23.2@58.527,325.623 58.527,308.073 58.004,307.55 U3.3@56.769,307.55
NetC27_2: C27.2 C87.2 R78.2 U5.A6 U5.A7 U5.B6 U5.B7 U15.3 | length 59.6
  L1 w0.2: U5.A7@33.077,203.85 33.156,203.928 33.156,204.156 33.642,204.642 38.82,204.642 39.72,203.742 39.72,201.88 41,200.6 47.7,200.6 49.37,198.93 49.37,194.092 49.87,193.592 R78.2@51.72,193.592 ; R78.2@52.07,193.542 53.67,195.142 C27.2@56.87,195.142 57.97,195.142 58.32,194.792 C87.2@58.32,189.342 58.32,171.792 57.797,171.269 U15.3@56.562,171.269
NetC28_1: C28.1 R26.1 U4.G7 | length 6.7
  L1 w0.2: U4.G7@33.284,332.511 33.309,332.536 33.89,332.536 34.877,333.523 R26.1@35.577,333.523 35.527,333.573 C28.1@35.527,337.523
NetC29_1: C29.1 R27.1 U5.G7 | length 6.6
  L1 w0.2: U5.G7@33.102,196.255 33.683,196.255 34.67,197.242 R27.1@35.37,197.242 ; R27.1@35.32,197.292 C29.1@35.32,201.242
NetC31_2: C31.2 C64.2 R53.2 U6.A6 U6.A7 U6.B6 U6.B7 U12.3 | length 59.7
  L1 w0.2: U6.A7@33.387,271.124 33.466,271.202 33.466,271.466 33.916,271.916 39.13,271.916 40.03,271.016 40.03,268.97 41.1,267.9 47.8,267.9 49.68,266.02 49.68,261.366 50.18,260.866 R53.2@52.03,260.866 ; R53.2@52.38,260.816 53.98,262.416 C31.2@57.18,262.416 58.28,262.416 58.63,262.066 C64.2@58.63,256.616 58.63,239.066 58.107,238.543 U12.3@56.872,238.543
NetC33_2: C33.2 C110.2 R103.2 U7.A6 U7.A7 U7.B6 U7.B7 U18.3 | length 58.8
  L1 w0.2: U7.A7@33.007,132.758 38.842,132.758 39.824,131.776 39.824,130.876 41.4,129.3 48.2,129.3 49.474,128.026 49.474,122.753 49.974,122.253 R103.2@51.824,122.253 ; R103.2@52.174,122.203 53.774,123.803 C33.2@56.974,123.803 58.074,123.803 58.424,123.453 C110.2@58.424,118.003 58.424,100.453 57.901,99.93 U18.3@56.666,99.93
NetC34_1: C34.1 R28.1 U6.G7 | length 6.6
  L1 w0.2: U6.G7@33.412,263.529 33.993,263.529 34.98,264.516 R28.1@35.68,264.516 ; R28.1@35.63,264.566 C34.1@35.63,268.516
NetC35_1: C35.1 R29.1 U7.G7 | length 6.1
  L1 w0.2: U7.G7@33.007,125.138 34.93,125.138 34.95,125.158 34.95,127.925 34.924,127.951 C35.1@34.924,129.26
NetC40_2: C40.2 U9.14 | length 4.5
  L1 w0.2: U9.14@40.411,77.113 40.461,77.063 41.487,77.063 42.486,76.064 44.314,76.064 C40.2@44.4,76.15
NetC41_1: C41.1 R33.1 U8.G7 | length 7.2
  L1 w0.2: U8.G7@33.42,51.61 35.01,51.61 35.9,52.5 R33.1@35.9,52.65 C41.1@35.9,56.9
NetC52_1: C52.1 R34.2
  other v1: 150.5,229.5 153.25,229.5 150.5,235 153.25,235
NetC52_2: C52.2 C53.2 NMOS2.9 NMOS2.10 NMOS2.11 NMOS2.12 NMOS2.13 NMOS2.14 NMOS2.15 NMOS2.16 TRAN2.4
  other v1: 118.25,228.75 121.25,228.75 176.25,231 179,231 118.25,231.5 121.25,231.5 176.25,233.75 179,233.75 174.5,245.25 177.25,245.25 174.5,248 177.25,248
NetC53_1: C53.1 PMOS2.5 PMOS2.6 PMOS2.7 PMOS2.8 R34.1
  other v1: 137.5,238.75 140.25,238.75 137.5,241.5 140.25,241.5
NetC55_1: C55.1 U10.32 | length 4.2
  L1 w0.2: U10.32@38.61,245.346 41.08,247.816 C55.1@41.78,247.816
NetC55_2: C55.2 D7.2 R36.1 R37.2 | length 12.7
  L1 w0.2: C55.2@43.38,247.916 R37.2@47.63,247.916 50.975,247.916 51.059,248 53.275,248 53.459,247.816 R36.1@55.93,247.816
NetC56_2: C56.2 U10.26 | length 5.1
  L1 w0.2: U10.26@38.57,242.216 41.486,239.3 41.65,239.3 42,238.95 C56.2@42,238.6
NetC57_1: C57.1 R44.1 U11.3 U12.1 | length 38.8
  L1 w0.2: U11.3@38.152,252.223 38.652,252.223 38.877,251.998 38.877,251.942 38.994,251.825 39.439,251.825 v2(39.83,252.216) ; C57.1@55.33,233.616 R44.1@57.43,233.616 U12.1@57.43,235.778 ; U12.1@56.872,236.003 57.31,236.003 58.473,237.166 58.473,237.348 v2(58.55,237.425)
  L6 w0.2: v2(39.83,252.216) 41.575,250.471 41.575,241.45 45.6,237.425 v2(58.55,237.425)
NetC57_2: C57.2 C60.2 R45.1 R52.2 U12.8 | length 424.4
  L1 w0.2: v2(49.6,236.8) 50.397,236.003 U12.8@51.448,236.003 51.448,234.348 C60.2@52.23,233.566 52.28,233.616 C57.2@54.322,233.616 ; R45.1@358.7,254.75 358.85,254.6 360.892,254.6 361.117,254.825 362.275,254.825 362.4,254.7 362.4,254.65 362.55,254.5 R52.2@362.6,254.5
  L6 w0.2: v2(49.6,236.8) 44.85,236.8 40.925,240.725 40.925,244.575 33.125,252.375 33.125,279.6 40.1,286.575 67.503,286.575 ccw(c68,287.5) 68.497,286.575 72.253,286.575 ccw(c72.75,287.5) 73.247,286.575 77.003,286.575 ccw(c77.5,287.5) 77.997,286.575 82.003,286.575 ccw(c82.5,287.5) 82.997,286.575 86.753,286.575 ccw(c87.25,287.5) 87.747,286.575 91.503,286.575 ccw(c92,287.5) 92.497,286.575 294.428,286.575 294.486,286.516 295.25,285.753 295.25,257.375 298.025,254.6 v2(360.8,254.6)
NetC58_1: C58.1 R47.1 U11.4 | length 5.2
  L1 w0.2: U11.4@38.23,253.571 C58.1@38.23,256.266 R47.1@40.78,256.266
NetC58_2: C58.2 C63.2 D8.1 R47.2 R53.1 | length 4.3
  L1 w0.2: R53.1@46.58,260.816 C63.2@46.58,265.066
NetC59_2: C59.2 U10.7 | length 4.7
  L1 w0.2: C59.2@27.838,246.316 28.938,245.216 U10.7@32.13,245.216
NetC60_1: C60.1 R44.2 | length 5.4
  L1 w0.2: C60.1@52.23,232.066 56.83,232.066 57.38,232.616 R44.2@57.43,232.616
NetC61_2: C61.2 U10.17 | length 12.1
  L1 w0.2: U10.17@32.13,240.216 31.03,240.216 30.73,239.916 30.73,238.816 32.772,236.773 37.151,236.773 38.03,235.895 C61.2@38.03,234.966
NetC62_2: C62.2 R41.1 U11.1 | length 8.5
  L1 w0.2: C62.2@27.68,256.916 28.03,256.566 28.179,256.566 31.252,253.493 U11.1@31.752,253.493 ; C62.2@27.68,257.116 27.95,257.386 27.95,258 28.45,258.5 R41.1@28.45,259.8
NetC75_1: C75.1 R59.2
  other v1: 150.75,160.5 153.5,160.5 150.75,166.75 153.5,166.75
NetC75_2: C75.2 C76.2 NMOS3.9 NMOS3.10 NMOS3.11 NMOS3.12 NMOS3.13 NMOS3.14 NMOS3.15 NMOS3.16 TRAN3.4
  other v1: 118,160 121,160 118,162.75 121,162.75 176.25,162.75 179,162.75 176.25,165.5 179,165.5 173.75,176.5 176.5,176.5 173.75,179.25 176.5,179.25
NetC76_1: C76.1 PMOS3.5 PMOS3.6 PMOS3.7 PMOS3.8 R59.1
  other v1: 137.5,171 140.25,171 137.5,173.75 140.25,173.75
